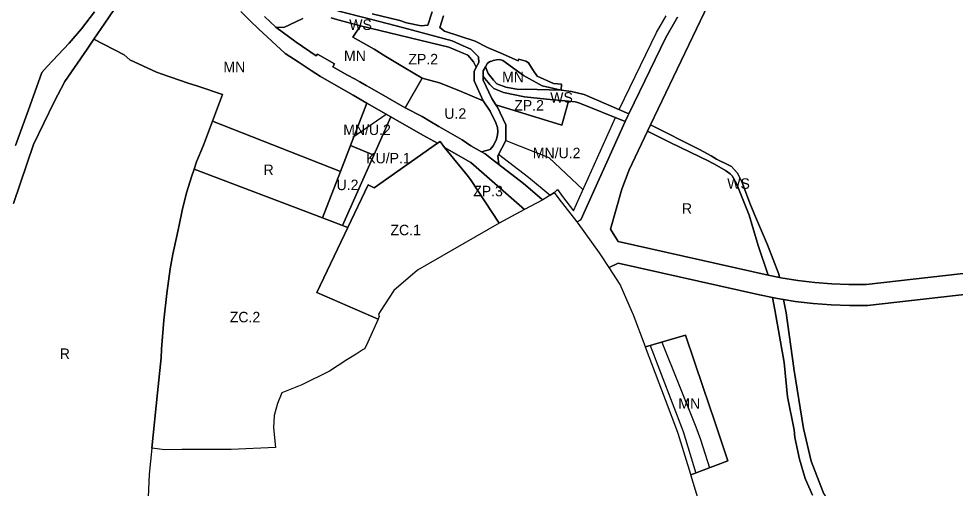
# Model space of a CAD drawing. Extents: x 7438199 to 7440548, y 5549253 to 5551017.
# Drawn here: x 7438706 to 7439598, y 5549912 to 5550360 of the extents above; entities that cross this region are included whole.
import ezdxf

# ---------------------------------------------------------------- set-up
doc = ezdxf.new("R2010")
doc.units = 0
for name, color, linetype in [('linie_rozgraniczajace', 7, 'Continuous'), ('linie_zabudowy_nieprzekraczalne', 7, 'Continuous'), ('oznaczenia_przeznaczen', 7, 'Continuous')]:
    doc.layers.add(name, color=color, linetype=linetype)

msp = doc.modelspace()

# ---------------------------------------------------------------- linework, layer by layer
at = {"layer": 'linie_rozgraniczajace'}
for points in [[(7439365.78, 5550380.83), (7439307.43, 5550258.63), (7439304.62, 5550252.73), (7439287.04, 5550215.91), (7439280.01, 5550197.26), (7439269.28, 5550159.31), (7439276.79, 5550147.35), (7439419.48, 5550115.3), (7439430.28, 5550113.1), (7439431.67, 5550112.82), (7439447.73, 5550110.24), (7439463.89, 5550108.31), (7439480.12, 5550107.06), (7439496.38, 5550106.47), (7439512.65, 5550106.55), (7439708.69, 5550128.79)], [(7439708.69, 5550128.79), (7439512.65, 5550106.55), (7439496.38, 5550106.47), (7439480.12, 5550107.06), (7439463.89, 5550108.31), (7439447.73, 5550110.24), (7439431.67, 5550112.82), (7439430.28, 5550113.1), (7439429.75, 5550116.18), (7439418.73, 5550144.37), (7439406.35, 5550173.3), (7439405.77, 5550174.67), (7439402.16, 5550184.1), (7439397.91, 5550195.2), (7439394.5, 5550204.3), (7439390.14, 5550212.5), (7439387, 5550216.07), (7439384.5, 5550218.9), (7439382.56, 5550219.84), (7439370.31, 5550225.94), (7439365.18, 5550228.96), (7439354.06, 5550235.07), (7439307.43, 5550258.63), (7439365.78, 5550380.83)], [(7438796.75, 5550368.59), (7438787.79, 5550355.53), (7438777.36, 5550340.24), (7438770.95, 5550330.85), (7438749.93, 5550299.87), (7438739.58, 5550280.49), (7438719.95, 5550239.79), (7438700.83, 5550183.58)], [(7438778.11, 5550366.38), (7438765.62, 5550350.13), (7438753.88, 5550336.34), (7438733.09, 5550314.14), (7438728.07, 5550308.61), (7438716.44, 5550276.4), (7438702.92, 5550238.98)], [(7438702.92, 5550238.98), (7438716.44, 5550276.4), (7438728.07, 5550308.61), (7438733.09, 5550314.14), (7438753.88, 5550336.34), (7438765.62, 5550350.13), (7438778.11, 5550366.38)], [(7438917.29, 5550366.61), (7438926.4, 5550357.75), (7438934.3, 5550350.07), (7438959.55, 5550326.55), (7438971.96, 5550318.57), (7438984.37, 5550310.58), (7438993.28, 5550304.85), (7439010.4, 5550294.96), (7439024.32, 5550286.92), (7439037.39, 5550279.38), (7439021.85, 5550239.01), (7439012.26, 5550214.09), (7438890.4, 5550262.02), (7438899.92, 5550287.46), (7438876.56, 5550295.44), (7438867.12, 5550298.47), (7438850.87, 5550303.94), (7438848.02, 5550305.11), (7438837, 5550308.87), (7438811.83, 5550320.68), (7438806.26, 5550325.22), (7438777.36, 5550340.24), (7438787.79, 5550355.53), (7438796.75, 5550368.59)], [(7438939.98, 5550362.05), (7438950.72, 5550351.67), (7438969.97, 5550337.43), (7438989.18, 5550324.48), (7438990.25, 5550326.1), (7439006.64, 5550316.81), (7439005.16, 5550313.84), (7439019.09, 5550305.95), (7439026.24, 5550302.19), (7439030.59, 5550299.77), (7439036.6, 5550296.11), (7439040.28, 5550294.15), (7439057.43, 5550284.54), (7439073.98, 5550274.91), (7439090.18, 5550266.66), (7439097.37, 5550262.19), (7439105.88, 5550257.19), (7439128.16, 5550244.48), (7439136.55, 5550238.72), (7439146.63, 5550233.02), (7439150.12, 5550231.05), (7439156.03, 5550226.19), (7439162.92, 5550220.9), (7439186.49, 5550202.81), (7439203.95, 5550187.71), (7439205.09, 5550187.04), (7439187.46, 5550178.1), (7439136.51, 5550222.81), (7439111.35, 5550236.99), (7439107.14, 5550242.9), (7439104.56, 5550241.08), (7439090.56, 5550248.9), (7439060.28, 5550266.25), (7439037.39, 5550279.38), (7439024.32, 5550286.92), (7439010.4, 5550294.96), (7438993.28, 5550304.85), (7438984.37, 5550310.58), (7438971.96, 5550318.57), (7438959.55, 5550326.55), (7438934.3, 5550350.07), (7438926.4, 5550357.75), (7438917.29, 5550366.61)], [(7439009.39, 5550367.36), (7439040.93, 5550359.25), (7439072.46, 5550351.14), (7439118.59, 5550338.69), (7439129.21, 5550334.09), (7439136.48, 5550330.93), (7439143.58, 5550323.47), (7439143.97, 5550318.1), (7439141.62, 5550313.51), (7439138.85, 5550318.82), (7439133.6, 5550325.01), (7439115.54, 5550332.81), (7439031.2, 5550353.13), (7439009.74, 5550358.8), (7439003.36, 5550360.49)], [(7439166.52, 5550326.41), (7439181.35, 5550319.56), (7439182.07, 5550321.4), (7439188.87, 5550319.24), (7439191.43, 5550317.66), (7439195.51, 5550311.16), (7439199.57, 5550304.91), (7439215.21, 5550297.94), (7439222.78, 5550297.39), (7439222.28, 5550291.66), (7439204.21, 5550295.9), (7439186.68, 5550305.75), (7439166.97, 5550320.06), (7439163.75, 5550320.86), (7439160.72, 5550320.69), (7439159.23, 5550320.35), (7439157.73, 5550320.01), (7439156.3, 5550319.45), (7439154.86, 5550318.88), (7439152.19, 5550317.35), (7439150.38, 5550314.02), (7439148.2, 5550310.01), (7439148.09, 5550304.68), (7439148.01, 5550301.07), (7439156.24, 5550283.75), (7439160.29, 5550277.79), (7439161.76, 5550275.62), (7439169.81, 5550258.68), (7439169.68, 5550243.83), (7439161.98, 5550229.21), (7439162.92, 5550220.9), (7439156.03, 5550226.19), (7439150.12, 5550231.05), (7439146.63, 5550233.02), (7439154.78, 5550235.11), (7439157.67, 5550238.54), (7439160.54, 5550244.2), (7439161.81, 5550248.93), (7439162.25, 5550252.46), (7439161.76, 5550256.25), (7439160.09, 5550260.49), (7439154.8, 5550271.63), (7439148.02, 5550281.61), (7439139.43, 5550300.49), (7439139.55, 5550309.46), (7439141.62, 5550313.51), (7439143.97, 5550318.1), (7439143.58, 5550323.47), (7439136.48, 5550330.93), (7439129.21, 5550334.09), (7439118.59, 5550338.69), (7439072.46, 5550351.14), (7439040.93, 5550359.25), (7439009.39, 5550367.36)], [(7439099.56, 5550366.37), (7439095.55, 5550353.74), (7439089.12, 5550353.07), (7439075.2, 5550355.9), (7439068.64, 5550358.03), (7439042.41, 5550364.47)], [(7439042.41, 5550364.47), (7439068.64, 5550358.03), (7439075.2, 5550355.9), (7439089.12, 5550353.07), (7439095.55, 5550353.74), (7439099.56, 5550366.37)], [(7438976.46, 5550360.11), (7438958.22, 5550351.34), (7438950.72, 5550351.67), (7438939.98, 5550362.05)], [(7439003.36, 5550360.49), (7439009.74, 5550358.8), (7439031.2, 5550353.13), (7439023.96, 5550342.33), (7439044.35, 5550330.65), (7439055.54, 5550323.74), (7439072.77, 5550313.39), (7439090.06, 5550302.98), (7439073.98, 5550274.91), (7439057.43, 5550284.54), (7439040.28, 5550294.15), (7439036.6, 5550296.11), (7439030.59, 5550299.77), (7439026.24, 5550302.19), (7439019.09, 5550305.95), (7439005.16, 5550313.84), (7439006.64, 5550316.81), (7438990.25, 5550326.1), (7438989.18, 5550324.48), (7438969.97, 5550337.43), (7438950.72, 5550351.67), (7438958.22, 5550351.34), (7438976.46, 5550360.11)], [(7439333.09, 5550361.29), (7439322.11, 5550341.92), (7439286.73, 5550269.11), (7439277.32, 5550273.24), (7439244.44, 5550287.69), (7439232.14, 5550290.43), (7439222.28, 5550291.66), (7439222.78, 5550297.39), (7439215.21, 5550297.94), (7439199.57, 5550304.91), (7439195.51, 5550311.16), (7439191.43, 5550317.66), (7439188.87, 5550319.24), (7439182.07, 5550321.4), (7439181.35, 5550319.56), (7439166.52, 5550326.41), (7439152.25, 5550332.22), (7439140.68, 5550338.42), (7439126.05, 5550343.25), (7439111.42, 5550348.08), (7439106.84, 5550351.42), (7439110.46, 5550362.5)], [(7439110.46, 5550362.5), (7439106.84, 5550351.42), (7439111.42, 5550348.08), (7439126.05, 5550343.25), (7439140.68, 5550338.42), (7439152.25, 5550332.22), (7439166.52, 5550326.41)], [(7439670.68, 5550104.35), (7439514.05, 5550086.59), (7439496.81, 5550086.46), (7439479.57, 5550087.06), (7439462.38, 5550088.37), (7439445.25, 5550090.39), (7439434.01, 5550092.19), (7439428.23, 5550093.12), (7439423.54, 5550094.08), (7439411.33, 5550096.56), (7439276.65, 5550126.88), (7439268.13, 5550122.73), (7439260.27, 5550134.86), (7439259.05, 5550136.55), (7439238.61, 5550164.93), (7439237.69, 5550166.1), (7439241.27, 5550167.97), (7439283.42, 5550261.87), (7439285.9, 5550267.39), (7439286.73, 5550269.11), (7439322.11, 5550341.92), (7439333.09, 5550361.29)], [(7438700.83, 5550183.58), (7438719.95, 5550239.79), (7438739.58, 5550280.49), (7438749.93, 5550299.87), (7438770.95, 5550330.85), (7438777.36, 5550340.24), (7438806.26, 5550325.22), (7438811.83, 5550320.68), (7438837, 5550308.87), (7438848.02, 5550305.11), (7438850.87, 5550303.94), (7438867.12, 5550298.47), (7438876.56, 5550295.44), (7438899.92, 5550287.46), (7438890.4, 5550262.02), (7438881.89, 5550239.29), (7438875.17, 5550223.43), (7438872.87, 5550216.25), (7438870.57, 5550209.07), (7438865.97, 5550194.71), (7438861.76, 5550178.45), (7438858.4, 5550161.35), (7438858.18, 5550160.22), (7438856.67, 5550154.11), (7438852.82, 5550135.33), (7438850.05, 5550121.37), (7438846.83, 5550097.82), (7438844.02, 5550072.33), (7438842.02, 5550044.85), (7438841.48, 5550036.71), (7438838.17, 5550003.33), (7438832.74, 5549950.47), (7438830.01, 5549925.79), (7438827.02, 5549852.66)], [(7439357.84, 5549885.47), (7439345.79, 5549925.11), (7439381.15, 5549938.4), (7439368.28, 5549976.69), (7439357.64, 5550008.31), (7439340.9, 5550058.05), (7439302.66, 5550047.06), (7439290.92, 5550078.14), (7439290.4, 5550079.35), (7439278.56, 5550106.62), (7439268.13, 5550122.73), (7439276.65, 5550126.88), (7439411.33, 5550096.56), (7439423.54, 5550094.08), (7439425.74, 5550082.33), (7439434.64, 5550032.29), (7439438.03, 5549999.34), (7439444.29, 5549968.09), (7439444.82, 5549960.79), (7439449.18, 5549939.99), (7439454.65, 5549921.6), (7439461.84, 5549905.59)], [(7439606.18, 5549758.61), (7439574.15, 5549782.83), (7439550.33, 5549802), (7439536.49, 5549812.69), (7439524.42, 5549825.6), (7439514.03, 5549839.75), (7439508.38, 5549849.1), (7439503.53, 5549857.03), (7439491.93, 5549876), (7439471.74, 5549908.46), (7439460.34, 5549937.99), (7439453.06, 5549969.08), (7439443.91, 5550026.51), (7439443.9, 5550026.58), (7439436.61, 5550079.32), (7439435.31, 5550085.77), (7439434.01, 5550092.19), (7439445.25, 5550090.39), (7439462.38, 5550088.37), (7439479.57, 5550087.06), (7439496.81, 5550086.46), (7439514.05, 5550086.59), (7439670.68, 5550104.35)], [(7439461.84, 5549905.59), (7439454.65, 5549921.6), (7439449.18, 5549939.99), (7439444.82, 5549960.79), (7439444.29, 5549968.09), (7439438.03, 5549999.34), (7439434.64, 5550032.29), (7439425.74, 5550082.33), (7439423.54, 5550094.08), (7439428.23, 5550093.12), (7439434.01, 5550092.19), (7439435.31, 5550085.77), (7439436.61, 5550079.32), (7439443.9, 5550026.58), (7439443.91, 5550026.51), (7439453.06, 5549969.08), (7439460.34, 5549937.99), (7439471.74, 5549908.46)]]:
    msp.add_lwpolyline(points, dxfattribs=at)
for points in [[(7439023.96, 5550342.33), (7439031.2, 5550353.13), (7439115.54, 5550332.81), (7439133.6, 5550325.01), (7439138.85, 5550318.82), (7439141.62, 5550313.51), (7439139.55, 5550309.46), (7439139.43, 5550300.49), (7439148.02, 5550281.61), (7439124.86, 5550291.28), (7439106.62, 5550298.7), (7439090.06, 5550302.98), (7439072.77, 5550313.39), (7439055.54, 5550323.74), (7439044.35, 5550330.65)], [(7439150.38, 5550314.02), (7439152.19, 5550317.35), (7439154.86, 5550318.88), (7439156.3, 5550319.45), (7439157.73, 5550320.01), (7439159.23, 5550320.35), (7439160.72, 5550320.69), (7439163.75, 5550320.86), (7439166.97, 5550320.06), (7439186.68, 5550305.75), (7439204.21, 5550295.9), (7439222.28, 5550291.66), (7439188.07, 5550292.77), (7439181.81, 5550292.42), (7439169.74, 5550294.69), (7439161.04, 5550297.85), (7439157.84, 5550301.12), (7439153.01, 5550307.64)], [(7439148.09, 5550304.68), (7439148.2, 5550310.01), (7439150.38, 5550314.02), (7439153.01, 5550307.64), (7439157.84, 5550301.12), (7439161.04, 5550297.85), (7439169.74, 5550294.69), (7439181.81, 5550292.42), (7439188.07, 5550292.77), (7439222.28, 5550291.66), (7439232.14, 5550290.43), (7439244.44, 5550287.69), (7439277.32, 5550273.24), (7439286.73, 5550269.11), (7439285.9, 5550267.39), (7439283.42, 5550261.87), (7439239.21, 5550279.71), (7439235.58, 5550280.46), (7439229.45, 5550281.17), (7439208.42, 5550283.24), (7439187.4, 5550285.31), (7439167.6, 5550289.37), (7439158.35, 5550293.21), (7439154.4, 5550297.08)], [(7439073.98, 5550274.91), (7439090.06, 5550302.98), (7439106.62, 5550298.7), (7439124.86, 5550291.28), (7439148.02, 5550281.61), (7439154.8, 5550271.63), (7439160.09, 5550260.49), (7439161.76, 5550256.25), (7439162.25, 5550252.46), (7439161.81, 5550248.93), (7439160.54, 5550244.2), (7439157.67, 5550238.54), (7439154.78, 5550235.11), (7439146.63, 5550233.02), (7439136.55, 5550238.72), (7439128.16, 5550244.48), (7439105.88, 5550257.19), (7439097.37, 5550262.19), (7439090.18, 5550266.66)], [(7439148.01, 5550301.07), (7439148.09, 5550304.68), (7439154.4, 5550297.08), (7439158.35, 5550293.21), (7439167.6, 5550289.37), (7439187.4, 5550285.31), (7439208.42, 5550283.24), (7439229.45, 5550281.17), (7439223.17, 5550258.19), (7439160.29, 5550277.79), (7439156.24, 5550283.75)], [(7439021.85, 5550239.01), (7439037.39, 5550279.38), (7439060.28, 5550266.25), (7439044.03, 5550229.85)], [(7439161.98, 5550229.21), (7439169.68, 5550243.83), (7439169.81, 5550258.68), (7439161.76, 5550275.62), (7439160.29, 5550277.79), (7439223.17, 5550258.19), (7439229.45, 5550281.17), (7439235.58, 5550280.46), (7439239.21, 5550279.71), (7439283.42, 5550261.87), (7439241.27, 5550167.97), (7439237.69, 5550166.1), (7439220.44, 5550188.01), (7439216.08, 5550194.32), (7439205.09, 5550187.04), (7439203.95, 5550187.71), (7439186.49, 5550202.81), (7439162.92, 5550220.9)], [(7439014.1, 5550162.86), (7439044.03, 5550229.85), (7439060.28, 5550266.25), (7439090.56, 5550248.9), (7439104.56, 5550241.08), (7439044.48, 5550198.67), (7439038.79, 5550201.4), (7439019.42, 5550160.85)], [(7438872.87, 5550216.25), (7438875.17, 5550223.43), (7438881.89, 5550239.29), (7438890.4, 5550262.02), (7439012.26, 5550214.09), (7438995.28, 5550169.98)], [(7439304.62, 5550252.73), (7439307.43, 5550258.63), (7439354.06, 5550235.07), (7439365.18, 5550228.96), (7439370.31, 5550225.94), (7439382.56, 5550219.84), (7439384.5, 5550218.9), (7439387, 5550216.07), (7439390.14, 5550212.5), (7439394.5, 5550204.3), (7439397.91, 5550195.2), (7439402.16, 5550184.1), (7439405.77, 5550174.67), (7439406.35, 5550173.3), (7439418.73, 5550144.37), (7439429.75, 5550116.18), (7439430.28, 5550113.1), (7439419.48, 5550115.3), (7439410.1, 5550143.69), (7439401.47, 5550172.54), (7439389.31, 5550202.67), (7439385.3, 5550210.06), (7439383.27, 5550211.99), (7439378.99, 5550215.22), (7439368.25, 5550221.15), (7439365.89, 5550222.41), (7439363.09, 5550223.9), (7439326.9, 5550241.63)], [(7439269.28, 5550159.31), (7439280.01, 5550197.26), (7439287.04, 5550215.91), (7439304.62, 5550252.73), (7439326.9, 5550241.63), (7439363.09, 5550223.9), (7439365.89, 5550222.41), (7439368.25, 5550221.15), (7439378.99, 5550215.22), (7439383.27, 5550211.99), (7439385.3, 5550210.06), (7439389.31, 5550202.67), (7439401.47, 5550172.54), (7439410.1, 5550143.69), (7439419.48, 5550115.3), (7439276.79, 5550147.35)], [(7438989.89, 5550099), (7439019.42, 5550160.85), (7439038.79, 5550201.4), (7439044.48, 5550198.67), (7439104.56, 5550241.08), (7439107.14, 5550242.9), (7439111.35, 5550236.99), (7439133, 5550210.66), (7439135.95, 5550206.56), (7439163.28, 5550165.05), (7439085.53, 5550120.17), (7439063.04, 5550100.73), (7439050.19, 5550080.7), (7439048.57, 5550078.18), (7439049.05, 5550075.9), (7439048.03, 5550073.58)], [(7438995.28, 5550169.98), (7439012.26, 5550214.09), (7439021.85, 5550239.01), (7439044.03, 5550229.85), (7439014.1, 5550162.86)], [(7439111.35, 5550236.99), (7439136.51, 5550222.81), (7439187.46, 5550178.1), (7439163.28, 5550165.05), (7439135.95, 5550206.56), (7439133, 5550210.66)], [(7438832.74, 5549950.47), (7438838.17, 5550003.33), (7438841.48, 5550036.71), (7438842.02, 5550044.85), (7438844.02, 5550072.33), (7438846.83, 5550097.82), (7438850.05, 5550121.37), (7438852.82, 5550135.33), (7438856.67, 5550154.11), (7438858.18, 5550160.22), (7438858.4, 5550161.35), (7438861.76, 5550178.45), (7438865.97, 5550194.71), (7438870.57, 5550209.07), (7438872.87, 5550216.25), (7438995.28, 5550169.98), (7439014.1, 5550162.86), (7439019.42, 5550160.85), (7438989.89, 5550099), (7439048.03, 5550073.58), (7439038.35, 5550051.48), (7439035.22, 5550044.94), (7439033.75, 5550044.5), (7439027.12, 5550040), (7439018.29, 5550034.62), (7439001.79, 5550023.9), (7438975.53, 5550010.92), (7438956.51, 5550003.07), (7438952.16, 5549993.13), (7438949.09, 5549981.56), (7438948.45, 5549969.83), (7438950.4, 5549951.18), (7438908.08, 5549949.25), (7438893.23, 5549949.11), (7438878.83, 5549949.14), (7438861.36, 5549949.29), (7438845.04, 5549948.9)], [(7439302.66, 5550047.06), (7439340.9, 5550058.05), (7439357.64, 5550008.31), (7439368.28, 5549976.69), (7439381.15, 5549938.4), (7439345.79, 5549925.11), (7439345.71, 5549925.37), (7439333.77, 5549964.62), (7439333.57, 5549965.17), (7439333.46, 5549965.44), (7439321.68, 5549996.68), (7439302.73, 5550046.87)]]:
    msp.add_lwpolyline(points, close=True, dxfattribs=at)
at = {"layer": 'linie_zabudowy_nieprzekraczalne'}
for points in [[(7439277.61, 5550273.22), (7439313.26, 5550346.57), (7439322.46, 5550362.65)], [(7439024.08, 5550246.75), (7439055.83, 5550268.9)], [(7439162.8, 5550230.77), (7439191.36, 5550208.85), (7439211.81, 5550191.49), (7439216.08, 5550194.32), (7439219.05, 5550196.87), (7439223.57, 5550190.32), (7439234.25, 5550176.75), (7439274.14, 5550265.61)], [(7439169.68, 5550243.83), (7439210.7, 5550227.67), (7439243.25, 5550196.78)], [(7439318.3, 5550051.55), (7439350.54, 5549970.81), (7439355.04, 5549958.87), (7439363.75, 5549931.86)], [(7439307.26, 5550048.38), (7439338.51, 5549966.23), (7439350.49, 5549926.82)]]:
    msp.add_lwpolyline(points, dxfattribs=at)

# ---------------------------------------------------------------- texts
at = {"layer": 'oznaczenia_przeznaczen'}
for s, p in [('WS', (7439020.62, 5550349.07)), ('MN', (7439015.62, 5550319.5)), ('MN', (7438900.87, 5550308.77)), ('ZP.2', (7439076.93, 5550316.3)), ('MN', (7439166.16, 5550299.29)), ('WS', (7439211.99, 5550279.74)), ('U.2', (7439111.2, 5550264.41)), ('ZP.2', (7439177.73, 5550272.3)), ('MN/U.2', (7439014.88, 5550248.97)), ('KU/P.1', (7439036.8, 5550221.95)), ('MN/U.2', (7439195.44, 5550226.81)), ('R', (7438939.04, 5550210.72)), ('U.2', (7439008.58, 5550196.43)), ('WS', (7439380.53, 5550197.67)), ('ZP.3', (7439138.67, 5550190.55)), ('R', (7439337.38, 5550173.87)), ('ZC.1', (7439059.85, 5550153.41)), ('ZC.2', (7438906.89, 5550070.43)), ('R', (7438745, 5550035.51)), ('MN', (7439333.97, 5549987.98))]:
    msp.add_text(s, height=10, dxfattribs=at).set_placement(p)

doc.saveas('drawing.dxf')
